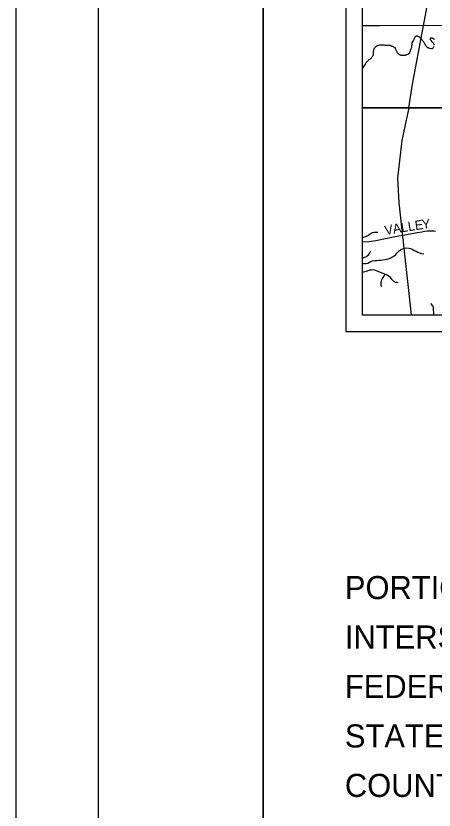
# Model space of a CAD drawing. Extents: x 0 to 34, y 0 to 22.
# Drawn here: x 0 to 2.535, y 11.097 to 15.914 of the extents above; entities that cross this region are included whole.
import ezdxf

# ---------------------------------------------------------------- set-up
doc = ezdxf.new("R2010")
doc.units = 0
for name, color, linetype in [('GM_X_County_Road', 7, 'Continuous'), ('GM_X_County_Road_Text', 7, 'Continuous'), ('GM_X_County_Text', 7, 'Continuous'), ('GM_X_Minor_River', 7, 'Continuous'), ('GM_X_Rail_Line', 7, 'Continuous'), ('GM_X_Township_Road', 7, 'Continuous'), ('SH_Border', 7, 'Continuous'), ('SH_Cut_Line', 7, 'Continuous'), ('SH_Data', 7, 'Continuous'), ('SH_Text', 7, 'Continuous')]:
    doc.layers.add(name, color=color, linetype=linetype)

msp = doc.modelspace()

# ---------------------------------------------------------------- linework, layer by layer
at = {"layer": 'GM_X_County_Road'}
for points in [[(2.1, 15.8557), (2.1056, 15.8557), (2.1223, 15.8558), (2.1364, 15.8559), (2.1528, 15.856), (2.1692, 15.8561), (2.1875, 15.8562), (2.2044, 15.8563), (2.6453, 15.8573)], [(2.1, 15.3588), (2.2191, 15.3582), (2.2365, 15.3581), (2.2986, 15.3576), (2.3228, 15.3572), (2.4078, 15.3566), (2.4112, 15.3565), (2.4919, 15.3563), (2.5957, 15.3565)], [(2.4356, 14.5987), (2.4317, 14.598), (2.413, 14.5943), (2.2999, 14.5731), (2.1821, 14.5495), (2.1399, 14.5446), (2.1, 14.5425)], [(2.5446, 14.6062), (2.5328, 14.6077), (2.5211, 14.6079), (2.5105, 14.6081), (2.4934, 14.6077), (2.4773, 14.606), (2.46, 14.6033), (2.4356, 14.5987)]]:
    msp.add_lwpolyline(points, dxfattribs=at)
at = {"layer": 'GM_X_County_Text'}
msp.add_lwpolyline([(2.1, 20.9), (2.1, 15.3556), (2.5967, 15.3568), (2.8413, 15.3568), (3.0143, 15.3554), (3.32, 15.3518), (3.6529, 15.3542), (3.8077, 15.3535), (4.1171, 15.3509), (4.1892, 15.3509), (4.3286, 15.3514), (4.5491, 15.3522), (4.6624, 15.3501), (5.0644, 15.3373), (5.4203, 15.3364), (5.4506, 15.3363), (5.4723, 15.3363), (5.5032, 15.3362), (5.5738, 15.336), (5.6184, 15.3359), (5.911, 15.3352), (6.0514, 15.3349), (6.6171, 15.3291), (8.9, 15.3047)], dxfattribs=at)
msp.add_lwpolyline([(2.1, 15.3556), (2.1, 14.1), (4.3787, 14.1), (4.3725, 14.1373), (4.3676, 14.1533), (4.4185, 14.2906), (4.4707, 14.5032), (4.0058, 14.5086), (4.0092, 14.8604), (4.002, 15.1777), (4.1154, 15.1803), (4.1171, 15.3509), (3.8077, 15.3535), (3.6529, 15.3542), (3.32, 15.3518), (3.0143, 15.3554), (2.8413, 15.3568), (2.5967, 15.3568)], close=True, dxfattribs=at)
at = {"layer": 'GM_X_Minor_River'}
for points in [[(2.3709, 15.6805), (2.375, 15.6824), (2.3792, 15.684), (2.3822, 15.6852), (2.3841, 15.6867), (2.3859, 15.689), (2.3878, 15.691), (2.3889, 15.694), (2.3904, 15.6978), (2.3919, 15.7013), (2.3929, 15.7062), (2.3951, 15.7116), (2.397, 15.7154), (2.3985, 15.7181), (2.3992, 15.7208), (2.3999, 15.7242), (2.4002, 15.7284), (2.4009, 15.7341), (2.4016, 15.7402), (2.4019, 15.7463), (2.403, 15.7516), (2.4096, 15.7639), (2.4111, 15.7658), (2.4126, 15.7681), (2.4137, 15.7708), (2.4152, 15.7746), (2.4167, 15.7792), (2.4185, 15.7822), (2.42, 15.7849), (2.4211, 15.7872), (2.4226, 15.7895), (2.4256, 15.7918), (2.4275, 15.7934), (2.4317, 15.7927), (2.4347, 15.7927), (2.437, 15.7916), (2.4393, 15.7901), (2.442, 15.7886), (2.4443, 15.7868), (2.4462, 15.7849), (2.4485, 15.7822), (2.4527, 15.7785), (2.4562, 15.7747), (2.46, 15.771), (2.4635, 15.7676), (2.4658, 15.7653), (2.4677, 15.7631), (2.4697, 15.7597), (2.4724, 15.7555), (2.4743, 15.7518), (2.4766, 15.7472), (2.479, 15.7427), (2.4817, 15.7382), (2.484, 15.7352), (2.4859, 15.7321), (2.4883, 15.7291), (2.4917, 15.7265), (2.4963, 15.7231), (2.502, 15.7202), (2.5081, 15.7183), (2.5211, 15.7159), (2.5234, 15.7159), (2.5252, 15.7167), (2.529, 15.7209), (2.5312, 15.7224), (2.5342, 15.7263), (2.5353, 15.729)], [(2.536, 15.7373), (2.5352, 15.74), (2.5344, 15.7434), (2.5324, 15.7476), (2.5297, 15.7513), (2.5274, 15.7536), (2.5243, 15.7558), (2.5224, 15.7577), (2.5209, 15.7596), (2.519, 15.7622), (2.5166, 15.7645), (2.5151, 15.7664), (2.5139, 15.7682), (2.5128, 15.7717), (2.5123, 15.7739), (2.5127, 15.777), (2.5134, 15.7789), (2.5157, 15.7816), (2.5176, 15.782), (2.5198, 15.7816), (2.5221, 15.7809), (2.5244, 15.7802), (2.5263, 15.7794), (2.5286, 15.7772), (2.5321, 15.7753), (2.5351, 15.7738), (2.5378, 15.772)], [(2.1, 15.5924), (2.1022, 15.5964), (2.107, 15.6041), (2.1111, 15.6098), (2.1144, 15.6148), (2.1171, 15.6183), (2.1189, 15.6229), (2.1215, 15.6271), (2.1237, 15.6305), (2.1256, 15.6328), (2.1275, 15.6351), (2.1297, 15.6375), (2.1327, 15.6405), (2.1353, 15.6436), (2.1383, 15.6459), (2.1417, 15.649), (2.1458, 15.6521), (2.15, 15.6544), (2.1552, 15.6598), (2.1578, 15.6637), (2.1612, 15.6679), (2.1638, 15.671), (2.1653, 15.6733), (2.1668, 15.6756), (2.1679, 15.6779), (2.1682, 15.6809), (2.1678, 15.6843), (2.1678, 15.6874), (2.1673, 15.6904), (2.1677, 15.6935), (2.168, 15.6969), (2.1687, 15.7007), (2.1698, 15.7041), (2.1709, 15.708), (2.1724, 15.7125), (2.1746, 15.7183), (2.1775, 15.7233), (2.1805, 15.726), (2.1835, 15.7294), (2.1854, 15.731), (2.1881, 15.7321), (2.1922, 15.7341), (2.1956, 15.7353), (2.2001, 15.7365), (2.2062, 15.7381), (2.2115, 15.7389), (2.216, 15.7393), (2.221, 15.739), (2.2248, 15.7387), (2.229, 15.7387), (2.2331, 15.738), (2.2377, 15.7373), (2.243, 15.737), (2.2476, 15.7367), (2.2521, 15.7364), (2.2578, 15.7364), (2.2628, 15.7365), (2.2666, 15.7362), (2.2692, 15.7358), (2.2711, 15.7351), (2.2734, 15.7336), (2.2761, 15.7325), (2.2799, 15.7314), (2.2829, 15.7307), (2.2875, 15.7277), (2.291, 15.7251), (2.2948, 15.7232), (2.2967, 15.7217), (2.2983, 15.7195), (2.2998, 15.7161), (2.3014, 15.7127), (2.3033, 15.7089), (2.3053, 15.704), (2.3073, 15.6994), (2.3096, 15.696), (2.3119, 15.6926), (2.3142, 15.6892), (2.3184, 15.6851), (2.3219, 15.6825), (2.3253, 15.6806), (2.3284, 15.6788), (2.3314, 15.6777), (2.3341, 15.677), (2.3372, 15.6762), (2.3417, 15.6759), (2.3485, 15.676), (2.3554, 15.6761), (2.3595, 15.6765), (2.3618, 15.6769), (2.3641, 15.6773), (2.366, 15.6774), (2.3679, 15.6785), (2.3709, 15.6805)], [(2.1, 14.567), (2.1054, 14.5713), (2.1209, 14.5768), (2.1367, 14.585), (2.1469, 14.5919), (2.1616, 14.6005), (2.1718, 14.6029), (2.1828, 14.603), (2.1934, 14.6027)], [(2.1, 14.4142), (2.1102, 14.4122), (2.1205, 14.4115), (2.1329, 14.4147), (2.1491, 14.4244), (2.1627, 14.4287), (2.1756, 14.4304), (2.1873, 14.4313), (2.1994, 14.433), (2.2131, 14.4335), (2.2237, 14.434), (2.2358, 14.4356), (2.2471, 14.4388), (2.2577, 14.4416), (2.2683, 14.4451), (2.28, 14.4506), (2.2909, 14.4568), (2.3029, 14.4672), (2.3115, 14.4768), (2.3261, 14.4914), (2.3378, 14.4995), (2.3559, 14.5062), (2.3696, 14.5067), (2.3828, 14.5057), (2.3927, 14.5024), (2.4057, 14.4972), (2.4152, 14.492), (2.4259, 14.4864), (2.4369, 14.4805), (2.4465, 14.476), (2.4598, 14.472), (2.473, 14.471)]]:
    msp.add_lwpolyline(points, dxfattribs=at)
at = {"layer": 'GM_X_Rail_Line'}
for points in [[(2.3828, 15.3572), (2.4036, 15.4999), (2.4892, 15.9504), (2.5052, 16.1024), (2.4992, 16.2334), (2.4726, 16.3585), (2.4359, 16.4747), (2.3792, 16.5945), (2.2851, 16.7329), (2.1, 17.0033)], [(2.3828, 15.3572), (2.3405, 15.1576), (2.3128, 14.9309), (2.3208, 14.7804), (2.3962, 14.1)]]:
    msp.add_lwpolyline(points, dxfattribs=at)
at = {"layer": 'GM_X_Township_Road'}
for points in [[(2.1, 15.3588), (2.2191, 15.3582), (2.2365, 15.3581), (2.2986, 15.3576), (2.3228, 15.3572), (2.4078, 15.3566), (2.4112, 15.3565), (2.4919, 15.3563), (2.5957, 15.3565)], [(2.1, 14.4449), (2.1162, 14.4501), (2.1248, 14.4547), (2.1304, 14.4587), (2.137, 14.4646), (2.1443, 14.4737), (2.1476, 14.4805), (2.1514, 14.4889)], [(2.1, 14.3589), (2.1239, 14.3659), (2.132, 14.3684), (2.1463, 14.3729), (2.1539, 14.3744), (2.1621, 14.3751), (2.1724, 14.3744), (2.1838, 14.3708), (2.2386, 14.348), (2.2502, 14.343), (2.2568, 14.3392), (2.2619, 14.3359), (2.2667, 14.3313), (2.2712, 14.326), (2.2758, 14.3184), (2.2801, 14.3133), (2.2872, 14.3075), (2.2948, 14.3024), (2.3021, 14.2997), (2.31, 14.2981), (2.3166, 14.2964)], [(2.2163, 14.271), (2.2145, 14.2842), (2.2142, 14.2928), (2.2145, 14.2992), (2.216, 14.306), (2.2183, 14.3136), (2.2223, 14.3209), (2.2272, 14.3278), (2.231, 14.3326), (2.2386, 14.348)], [(2.5336, 14.1), (2.5313, 14.1459), (2.5282, 14.155), (2.5158, 14.1701)]]:
    msp.add_lwpolyline(points, dxfattribs=at)
at = {"layer": 'SH_Border'}
for points in [[(0.5, 21.5), (1.5, 21.5), (1.5, 0.5), (0.5, 0.5)], [(1.5, 21.5), (33.5, 21.5), (33.5, 0.5), (1.5, 0.5)]]:
    msp.add_lwpolyline(points, close=True, dxfattribs=at)
at = {"layer": 'SH_Cut_Line'}
msp.add_lwpolyline([(0, 0), (34, 0), (34, 22), (0, 22)], close=True, dxfattribs=at)
for points in [[(2.1, 20.9), (2.1, 15.3556), (2.5967, 15.3568), (2.8413, 15.3568), (3.0143, 15.3554), (3.32, 15.3518), (3.6529, 15.3542), (3.8077, 15.3535), (4.1171, 15.3509), (4.1892, 15.3509), (4.3286, 15.3514), (4.5491, 15.3522), (4.6624, 15.3501), (5.0644, 15.3373), (5.4203, 15.3364), (5.4506, 15.3363), (5.4723, 15.3363), (5.5032, 15.3362), (5.5738, 15.336), (5.6184, 15.3359), (5.911, 15.3352), (6.0514, 15.3349), (6.6171, 15.3291), (8.9, 15.3047)], [(2.5967, 15.3568), (2.1, 15.3556), (2.1, 14.1), (8.9, 14.1)]]:
    msp.add_lwpolyline(points, dxfattribs=at)
at = {"layer": 'SH_Data'}
for p, q in [((2, 21), (2, 14)), ((2.1, 20.9), (2.1, 14.1)), ((2.1, 14.1), (8.9, 14.1)), ((2, 14), (9, 14))]:
    msp.add_line(p, q, dxfattribs=at)

# ---------------------------------------------------------------- texts
at = {"layer": 'GM_X_County_Road_Text'}
for s, rotation, p in [('V', 10.8141, (2.2409, 14.5839)), ('A', 9.4707, (2.2896, 14.5932)), ('L', 8.8592, (2.3388, 14.6014)), ('L', 8.8423, (2.3808, 14.608)), ('E', 8.3956, (2.4227, 14.6145)), ('Y', 6.4689, (2.4642, 14.6206))]:
    msp.add_text(s, height=0.0568, rotation=rotation, dxfattribs=at).set_placement(p)
at = {"layer": 'SH_Text'}
for s, p in [('PORTION TO BE IMPROVED', (1.9944, 12.3767)), ('INTERSTATE HIGHWAY', (1.9944, 12.0767)), ('FEDERAL ROUTES', (1.9944, 11.7767)), ('STATE ROUTES', (1.9944, 11.4767)), ('COUNTY & TOWNSHIP ROADS', (1.9944, 11.1767))]:
    msp.add_text(s, height=0.14, dxfattribs=at).set_placement(p)

doc.saveas('drawing.dxf')
